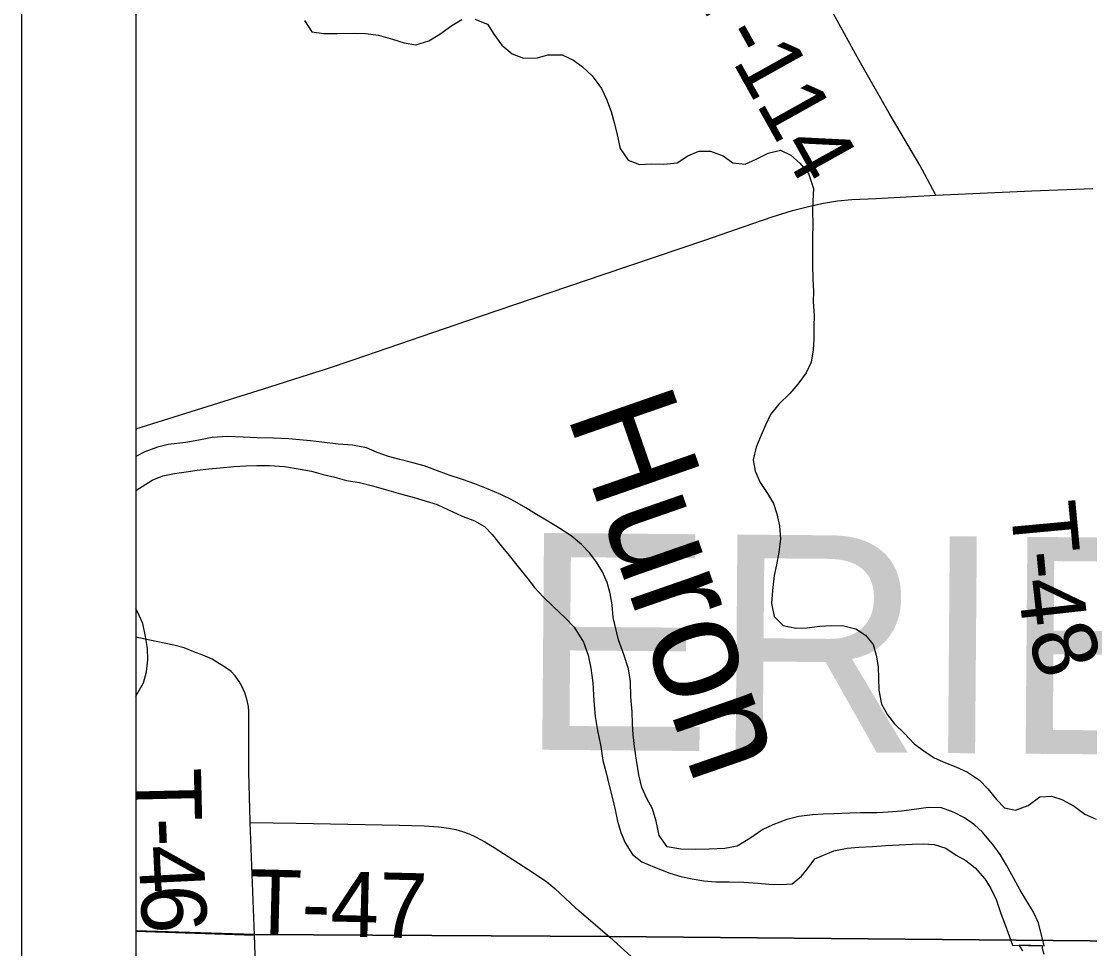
# Model space of a CAD drawing. Extents: x 0 to 34, y 0 to 22.
# Drawn here: x 21.64 to 22.573, y 15.383 to 16.194 of the extents above; entities that cross this region are included whole.
import ezdxf

# ---------------------------------------------------------------- set-up
doc = ezdxf.new("R2010")
doc.units = 0
for name, color, linetype in [('GM_X_County_Text', 7, 'Continuous'), ('GM_X_Major_River', 7, 'Continuous'), ('GM_X_Major_River_Text', 7, 'Continuous'), ('GM_X_Minor_River', 7, 'Continuous'), ('GM_X_Rail_Line', 7, 'Continuous'), ('GM_X_State_Route', 7, 'Continuous'), ('GM_X_Township_Road', 7, 'Continuous'), ('GM_X_Township_Road_Text', 7, 'Continuous'), ('SH_Cut_Line', 7, 'Continuous'), ('SH_Data', 7, 'Continuous')]:
    doc.layers.add(name, color=color, linetype=linetype)

msp = doc.modelspace()

# ---------------------------------------------------------------- linework, layer by layer
at = {"layer": 'GM_X_Major_River'}
msp.add_line((22.50595, 15.38653), (22.53371, 15.38591), dxfattribs=at)
for points in [[(22.53371, 15.38591), (22.5289, 15.40592), (22.52406, 15.41585), (22.51845, 15.42503), (22.51285, 15.43459), (22.50538, 15.44797), (22.5009, 15.45638), (22.4953, 15.46555), (22.48968, 15.47321), (22.47992, 15.4851), (22.47277, 15.49163), (22.4641, 15.4978), (22.45503, 15.50245), (22.44406, 15.50637), (22.4323, 15.50687), (22.42013, 15.50509), (22.40911, 15.50369), (22.39733, 15.50267), (22.38746, 15.50201), (22.37341, 15.50215), (22.36392, 15.50187), (22.35025, 15.50125), (22.34075, 15.50097), (22.33126, 15.5003), (22.31948, 15.4989), (22.30882, 15.49635), (22.29663, 15.49154), (22.28786, 15.48745), (22.27678, 15.47958), (22.26571, 15.47285), (22.25468, 15.47107), (22.24101, 15.47045), (22.22886, 15.47019), (22.21633, 15.47032), (22.20458, 15.47234), (22.19746, 15.48229), (22.19493, 15.49486), (22.19161, 15.50554), (22.18677, 15.51471), (22.1823, 15.52426), (22.17975, 15.5353), (22.17759, 15.54825), (22.17617, 15.55776), (22.17477, 15.57032), (22.1741, 15.57983), (22.17382, 15.59047), (22.1728, 15.6034), (22.17255, 15.61671), (22.17076, 15.62775), (22.1667, 15.64033), (22.16189, 15.6533), (22.15714, 15.67273), (22.15648, 15.68376), (22.15468, 15.69366), (22.15211, 15.70319), (22.14803, 15.71273), (22.14279, 15.72115), (22.13679, 15.72881), (22.12965, 15.73648), (22.12062, 15.74418), (22.11081, 15.75036), (22.09873, 15.7577), (22.09042, 15.76273), (22.08099, 15.76853), (22.06928, 15.77511), (22.05908, 15.78015), (22.04812, 15.78483), (22.03639, 15.78951), (22.0258, 15.79342), (22.01407, 15.79696), (22.00159, 15.80165), (21.99213, 15.80516), (21.98229, 15.80793), (21.97092, 15.8107), (21.96108, 15.81346), (21.95124, 15.81698), (21.94179, 15.82088), (21.92967, 15.82329), (21.91715, 15.82417), (21.90274, 15.82584), (21.89288, 15.82708), (21.8834, 15.82794), (21.87392, 15.8288), (21.86064, 15.82932), (21.84621, 15.82984), (21.83407, 15.83035), (21.82041, 15.83087), (21.80711, 15.82986), (21.79533, 15.82771), (21.78392, 15.82554), (21.76872, 15.8238), (21.75921, 15.82161), (21.74816, 15.81755), (21.7404, 15.81344)], [(21.7404, 15.78364), (21.75476, 15.79278), (21.7639, 15.79648), (21.77417, 15.79866), (21.78444, 15.80007), (21.79394, 15.8015), (21.8042, 15.80253), (21.81408, 15.80357), (21.82585, 15.80459), (21.83649, 15.80524), (21.84598, 15.80552), (21.85699, 15.80541), (21.87027, 15.80451), (21.88392, 15.80247), (21.89377, 15.80047), (21.90399, 15.79771), (21.91422, 15.79532), (21.92444, 15.79256), (21.93581, 15.79054), (21.94831, 15.78737), (21.95928, 15.78422), (21.9714, 15.78067), (21.98352, 15.77751), (22.00358, 15.7716), (22.0134, 15.76694), (22.02474, 15.7615), (22.03609, 15.75721), (22.04477, 15.75218), (22.05154, 15.74527), (22.05942, 15.7353), (22.06655, 15.72687), (22.07442, 15.71691), (22.08268, 15.70656), (22.08868, 15.6989), (22.09619, 15.69084), (22.10485, 15.68239), (22.11538, 15.6724), (22.12327, 15.66434), (22.1315, 15.65133), (22.13557, 15.63989), (22.13774, 15.62847), (22.13951, 15.61553), (22.1405, 15.59994), (22.14151, 15.58624), (22.14367, 15.57406), (22.14658, 15.55997), (22.14836, 15.54779), (22.15129, 15.53712), (22.15348, 15.52721), (22.15678, 15.51464), (22.15896, 15.50473), (22.16114, 15.49483), (22.16409, 15.48492), (22.16779, 15.47576), (22.17415, 15.46581), (22.18244, 15.45927), (22.19341, 15.45459), (22.20664, 15.44952), (22.21648, 15.44638), (22.22633, 15.44437), (22.23657, 15.44275), (22.24681, 15.44188), (22.25858, 15.44176), (22.27148, 15.44163), (22.28362, 15.44075), (22.29348, 15.43988), (22.30373, 15.4394), (22.3136, 15.44006), (22.32164, 15.44682), (22.32778, 15.45435), (22.33355, 15.4619), (22.34994, 15.46895), (22.36173, 15.47111), (22.37199, 15.47214), (22.38376, 15.47278), (22.39553, 15.47342), (22.40693, 15.47406), (22.41832, 15.47471), (22.4282, 15.47499), (22.43768, 15.47451), (22.4479, 15.47136), (22.45695, 15.46519), (22.46526, 15.46054), (22.47355, 15.454), (22.48181, 15.44441), (22.48705, 15.436), (22.49189, 15.42644), (22.49595, 15.41424), (22.49965, 15.40432), (22.50595, 15.38653)], [(21.7404, 15.60397), (21.74043, 15.60404), (21.747, 15.61576), (21.74975, 15.62523), (21.75099, 15.63586), (21.7507, 15.64574), (21.7489, 15.65602), (21.74635, 15.66745), (21.74189, 15.67776), (21.7404, 15.68041)]]:
    msp.add_lwpolyline(points, dxfattribs=at)
at = {"layer": 'GM_X_Minor_River'}
msp.add_line((22.53228, 15.38594), (22.5118, 15.3864), dxfattribs=at)
for points in [[(21.88764, 16.19425), (21.894, 16.18431), (21.90462, 16.18306), (21.91601, 16.18294), (21.93119, 16.18316), (21.94106, 16.18307), (21.95243, 16.18143), (21.96455, 16.17788), (21.97477, 16.17474), (21.985, 16.17311), (21.99642, 16.17642), (22.00597, 16.1824), (22.01629, 16.18989), (22.02507, 16.19512)], [(22.03646, 16.19539), (22.04743, 16.19109), (22.05304, 16.1823), (22.06016, 16.17272), (22.0692, 16.16503), (22.07903, 16.16151), (22.09118, 16.16176), (22.10032, 16.16433), (22.11285, 16.1642), (22.12267, 16.15954), (22.13059, 16.15376), (22.13887, 16.14607), (22.14711, 16.13497), (22.15158, 16.12542), (22.15565, 16.11474), (22.15859, 16.10407), (22.16077, 16.09454), (22.16331, 16.08235), (22.17043, 16.0724), (22.18026, 16.0685), (22.1909, 16.06915), (22.20152, 16.06866), (22.21331, 16.07006), (22.22247, 16.07605), (22.232, 16.08013), (22.24225, 16.08002), (22.25322, 16.07611), (22.26189, 16.06994), (22.27251, 16.06869), (22.28204, 16.07316), (22.29272, 16.07837), (22.30338, 16.08092), (22.31244, 16.07664), (22.32035, 16.06972), (22.32785, 16.06052), (22.33229, 16.04756), (22.3318, 16.03654), (22.33133, 16.02704), (22.33161, 16.01678), (22.3315, 16.00424), (22.33139, 15.99284), (22.33128, 15.98106), (22.33153, 15.96814), (22.33219, 15.95787), (22.3321, 15.94837), (22.33275, 15.93658), (22.33266, 15.92708), (22.33255, 15.91606), (22.33209, 15.90656), (22.33008, 15.89594), (22.32582, 15.88649), (22.31851, 15.87668), (22.3116, 15.86839), (22.30202, 15.85899), (22.29472, 15.84994), (22.29046, 15.84086), (22.28658, 15.83216), (22.28231, 15.82157), (22.27954, 15.81057), (22.28135, 15.80067), (22.28581, 15.79075), (22.29217, 15.78118), (22.2974, 15.77239), (22.30035, 15.76323), (22.30253, 15.75295), (22.30356, 15.74154), (22.30193, 15.72977), (22.29993, 15.71877), (22.29794, 15.70929), (22.2963, 15.69639), (22.29543, 15.685), (22.29798, 15.67357), (22.30588, 15.66589)], [(22.30588, 15.66589), (22.31687, 15.66349), (22.32636, 15.66378), (22.33776, 15.66518), (22.34839, 15.66583), (22.35864, 15.66534), (22.36925, 15.66295), (22.37754, 15.65717), (22.3843, 15.64912), (22.38687, 15.63997), (22.38867, 15.62969), (22.38896, 15.61981), (22.38924, 15.60916), (22.39178, 15.59697), (22.397, 15.5878), (22.403, 15.57976), (22.41165, 15.57131), (22.4203, 15.56248), (22.42859, 15.55631), (22.43764, 15.55014), (22.44747, 15.54586), (22.45655, 15.54234), (22.46675, 15.53768), (22.47732, 15.53073), (22.48446, 15.52305), (22.49196, 15.51386), (22.4991, 15.50656), (22.50857, 15.50456), (22.51962, 15.50863), (22.52994, 15.51613), (22.5402, 15.51678), (22.54928, 15.51365), (22.55985, 15.50784), (22.56928, 15.5009), (22.57911, 15.49662)], [(22.5118, 15.3864), (22.51178, 15.38581), (22.51365, 15.3835), (22.51476, 15.38159)], [(22.53368, 15.37825), (22.53224, 15.38359), (22.53227, 15.38549), (22.53228, 15.38594)]]:
    msp.add_lwpolyline(points, dxfattribs=at)
at = {"layer": 'GM_X_Rail_Line'}
for points in [[(21.7404, 20.42151), (21.7404, 15.39913), (21.84376, 15.39569), (22.15405, 15.39394), (22.79969, 15.38811), (22.81708, 15.3878), (22.79758, 16.0573), (22.79757, 16.06725), (22.79683, 16.0986), (22.79708, 16.13269), (22.79749, 16.14507), (22.79829, 16.15433), (22.7997, 16.16348), (22.80107, 16.16945), (22.8022, 16.174), (22.78887, 17.04474), (22.77639, 17.88363), (22.76822, 18.23412), (22.7679, 18.24823), (22.75894, 18.64947), (22.73442, 20.39832)], [(21.7404, 15.39913), (21.7404, 14.1), (22.8511, 14.1), (22.84358, 14.47408), (22.83864, 14.61592), (22.83423, 14.81058), (22.82389, 15.11203), (22.819, 15.30855), (22.81708, 15.3878), (22.79969, 15.38811), (22.15405, 15.39394), (21.84376, 15.39569)]]:
    msp.add_lwpolyline(points, close=True, dxfattribs=at)
at = {"layer": 'GM_X_State_Route'}
msp.add_lwpolyline([(21.7404, 15.83763), (21.79793, 15.85554), (21.8519, 15.87263), (21.89131, 15.88495), (21.90697, 15.89011), (21.93008, 15.89775), (22.04048, 15.93562), (22.14935, 15.97258), (22.23828, 16.00279), (22.26425, 16.01177), (22.29614, 16.02266), (22.31403, 16.02825), (22.32901, 16.03218), (22.34113, 16.03469), (22.35334, 16.03667), (22.36565, 16.03804), (22.38685, 16.03889), (22.41835, 16.04061), (22.43897, 16.04176), (22.52281, 16.04539), (22.57628, 16.0475)], dxfattribs=at)
at = {"layer": 'GM_X_Township_Road'}
for p, q in [((21.84398, 15.39514), (21.84015, 15.49368)), ((21.7404, 15.39858), (21.84398, 15.39514))]:
    msp.add_line(p, q, dxfattribs=at)
for points in [[(22.43897, 16.04176), (22.43389, 16.05155), (22.42501, 16.068), (22.39822, 16.11339), (22.37225, 16.15937), (22.34978, 16.20021), (22.31804, 16.25724), (22.27143, 16.34157), (22.17385, 16.51492), (22.0986, 16.65092), (22.09374, 16.65893), (22.08843, 16.66667), (22.08457, 16.6716), (22.07836, 16.67862), (22.06957, 16.68747), (22.04019, 16.71525), (21.9341, 16.81567), (21.87097, 16.87559), (21.8306, 16.9143), (21.82568, 16.91903)], [(21.84015, 15.49368), (21.84012, 15.49449), (21.83916, 15.53759), (21.839, 15.56648), (21.839, 15.59059), (21.83868, 15.5949), (21.8374, 15.60144), (21.83564, 15.60687), (21.83309, 15.61261), (21.83054, 15.61693), (21.82702, 15.62187), (21.8235, 15.62546), (21.81864, 15.62914), (21.81347, 15.63238), (21.80691, 15.63624), (21.79893, 15.63975), (21.79111, 15.64287), (21.78248, 15.64622), (21.7737, 15.64853), (21.75263, 15.653), (21.7404, 15.6556)], [(21.84015, 15.49368), (21.88042, 15.4931), (21.97059, 15.49139), (21.99232, 15.49078), (22.00467, 15.48993), (22.01383, 15.48869), (22.01984, 15.48741), (22.02576, 15.48572), (22.03153, 15.48361), (22.03714, 15.48107), (22.04532, 15.47673), (22.05325, 15.4719), (22.08692, 15.45014), (22.09936, 15.44169), (22.1064, 15.436), (22.11088, 15.43165), (22.12013, 15.42329), (22.12424, 15.41908), (22.12719, 15.41675), (22.15427, 15.39338)], [(21.86345, 14.88258), (21.86135, 14.94093), (21.85658, 15.07924), (21.84746, 15.29428), (21.84398, 15.39514)], [(22.83444, 14.81002), (22.83044, 14.81324), (22.75611, 14.87279), (22.72112, 14.90102), (22.68052, 14.93419), (22.65296, 14.95878), (22.62391, 14.9875), (22.57654, 15.03371), (22.52983, 15.07481), (22.43642, 15.14413), (22.36247, 15.19728), (22.32947, 15.21698), (22.31658, 15.22415), (22.27731, 15.24283), (22.26856, 15.24828), (22.2574, 15.25845), (22.23935, 15.28871), (22.19974, 15.34829), (22.18538, 15.36513), (22.15427, 15.39338)]]:
    msp.add_lwpolyline(points, dxfattribs=at)
at = {"layer": 'SH_Cut_Line'}
for points in [[(21.7404, 20.9), (21.7404, 15.39913), (21.84376, 15.39569), (22.15405, 15.39394), (22.79969, 15.38811), (22.81708, 15.3878), (23.80935, 15.36588), (24.21343, 15.36582), (24.72905, 15.3682)], [(24.72905, 15.3682), (24.21343, 15.36582), (23.80935, 15.36588), (22.81708, 15.3878), (22.79969, 15.38811), (22.15405, 15.39394), (21.84376, 15.39569), (21.7404, 15.39913), (21.7404, 14.1), (28.5404, 14.1)]]:
    msp.add_lwpolyline(points, dxfattribs=at)
at = {"layer": 'SH_Data'}
for p, q in [((21.6404, 21), (21.6404, 14)), ((21.7404, 20.9), (21.7404, 14.1))]:
    msp.add_line(p, q, dxfattribs=at)

# ---------------------------------------------------------------- texts
at = {"layer": 'GM_X_County_Text'}
msp.add_text('ERIE COUNTY', height=0.1893939, rotation=359.53411, dxfattribs=at).set_placement((22.07457, 15.55735))
at = {"layer": 'GM_X_Major_River_Text'}
msp.add_text('Huron', height=0.094752, rotation=289.18749, dxfattribs=at).set_placement((22.11638, 15.85058))
at = {"layer": 'GM_X_Township_Road_Text'}
for s, height, rotation, p in [('T-114', 0.056818, 299.16592, (22.22601, 16.22128)), ('T', 0.05682, 275.33043, (22.50417, 15.77166)), ('-', 0.05682, 275.43417, (22.50813, 15.72923)), ('4', 0.05682, 276.43928, (22.51046, 15.70492)), ('8', 0.05682, 290.50279, (22.51791, 15.65539)), ('T', 0.05682, 271.32008, (21.74046, 15.54042)), ('-', 0.05682, 272.33263, (21.74147, 15.49683)), ('4', 0.05682, 272.8157, (21.74244, 15.473)), ('T-47', 0.056818, 358.60494, (21.83822, 15.39612)), ('6', 0.05682, 273.06866, (21.74418, 15.43777))]:
    msp.add_text(s, height=height, rotation=rotation, dxfattribs=at).set_placement(p)

doc.saveas('drawing.dxf')
